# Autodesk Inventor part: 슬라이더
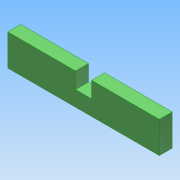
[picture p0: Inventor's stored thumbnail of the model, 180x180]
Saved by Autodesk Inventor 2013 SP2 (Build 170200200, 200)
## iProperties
Created: 2025-07
Part Number: 슬라이더
Material: Generic
Document SubType Name: Modeling
Designer: a
Density: 1 g/cm^3
변환 표준: STEP AP214IS
전처리기: Build: 200, Release: 2013 SP2 Update 6 - Date: Thu 07/17/2014
전송 단위: 밀리미터
불확실성: 0.01
Author: a
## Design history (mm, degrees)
node "슬라이더1"
node "솔리드1"
node "기준1"
